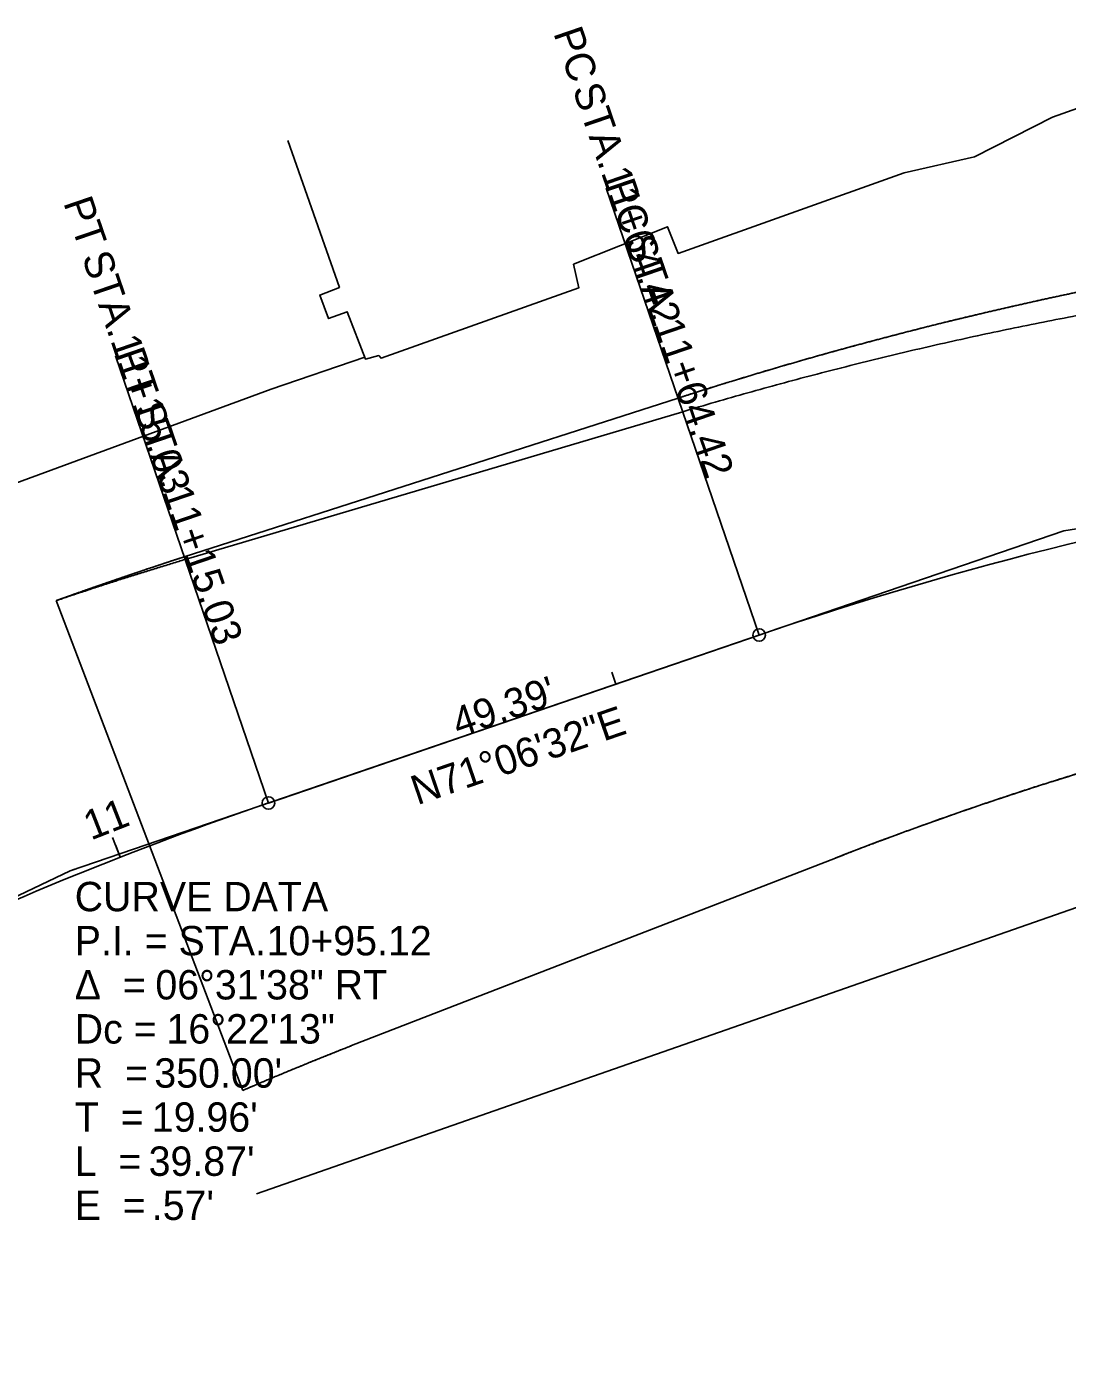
# Model space of a CAD drawing. Extents: x 219353 to 221640, y 361458 to 364236.
# Drawn here: x 220356.8 to 220456, y 362065.1 to 362191 of the extents above; entities that cross this region are included whole.
import ezdxf

# ---------------------------------------------------------------- set-up
doc = ezdxf.new("R2010")
doc.units = 0
for name, color, linetype in [('Default', 7, 'Continuous'), ('DR_P_Cells', 7, 'Continuous'), ('DR_P_GenericNode', 7, 'Continuous'), ('DR_X_Cells', 7, 'Continuous'), ('DR_X_GenericNode', 7, 'Continuous'), ('DR_X_Storm_Sewer', 7, 'Continuous'), ('DT_X_Contour_Major', 7, 'Continuous'), ('DT_X_Contour_Minor', 7, 'Continuous'), ('SC_ProfileRun1', 7, 'Continuous'), ('SC_ProfileRun2', 7, 'Continuous'), ('SC_ProfileRun3', 7, 'Continuous'), ('SC_Scratch1', 7, 'Continuous'), ('UT_X_San_Storm_Line', 7, 'Continuous'), ('UT_X_Sanitary_Cells', 7, 'Continuous'), ('UT_X_Sanitary_Line', 7, 'Continuous')]:
    doc.layers.add(name, color=color, linetype=linetype)

msp = doc.modelspace()

# ---------------------------------------------------------------- linework, layer by layer
at = {"layer": 'Default'}
for points in [[(220418.89, 362155.61), (220419.93, 362155.94), (220422, 362156.61), (220425.12, 362157.57), (220428.25, 362158.5), (220431.39, 362159.41), (220434.53, 362160.29), (220437.68, 362161.14), (220440.84, 362161.96), (220444, 362162.76), (220447.17, 362163.53), (220450.35, 362164.27), (220453.53, 362164.98), (220456.72, 362165.67), (220459.91, 362166.33), (220463.11, 362166.95), (220466.31, 362167.56), (220469.52, 362168.13), (220472.73, 362168.67), (220475.95, 362169.19), (220479.17, 362169.68), (220481.32, 362169.98), (220482.39, 362170.13)], [(220359.67, 362136.33), (220359.87, 362136.4), (220360.27, 362136.54), (220360.88, 362136.76), (220361.49, 362136.98), (220362.1, 362137.19), (220362.7, 362137.41), (220363.31, 362137.62), (220363.92, 362137.83), (220364.53, 362138.04), (220365.14, 362138.25), (220365.75, 362138.46), (220366.36, 362138.67), (220366.97, 362138.88), (220367.58, 362139.08), (220368.19, 362139.29), (220368.8, 362139.49), (220369.41, 362139.69), (220370.02, 362139.9), (220370.64, 362140.1), (220371.25, 362140.3), (220371.66, 362140.43), (220371.86, 362140.49)], [(220488.46, 362127.86), (220487.52, 362127.67), (220485.66, 362127.29), (220482.86, 362126.68), (220480.08, 362126.06), (220477.3, 362125.41), (220474.52, 362124.73), (220471.76, 362124.03), (220469, 362123.31), (220466.25, 362122.57), (220463.5, 362121.8), (220460.77, 362121.01), (220458.04, 362120.19), (220455.32, 362119.35), (220452.61, 362118.49), (220449.91, 362117.61), (220447.21, 362116.7), (220444.53, 362115.77), (220441.85, 362114.81), (220439.18, 362113.84), (220436.53, 362112.84), (220434.76, 362112.15), (220433.88, 362111.81)], [(220387.79, 362093.94), (220387.62, 362093.87), (220387.27, 362093.73), (220386.75, 362093.53), (220386.23, 362093.32), (220385.71, 362093.11), (220385.19, 362092.9), (220384.67, 362092.7), (220384.15, 362092.49), (220383.63, 362092.27), (220383.12, 362092.06), (220382.6, 362091.85), (220382.08, 362091.64), (220381.56, 362091.42), (220381.05, 362091.21), (220380.53, 362090.99), (220380.02, 362090.78), (220379.5, 362090.56), (220378.99, 362090.34), (220378.47, 362090.12), (220377.96, 362089.9), (220377.61, 362089.75), (220377.44, 362089.68)]]:
    msp.add_open_spline(points, degree=3, dxfattribs=at)
at = {"layer": 'DR_X_Cells'}
for p, q in [((220426.61, 362133.05), (220412.04, 362175.62)), ((220379.88, 362117.05), (220365.31, 362159.63))]:
    msp.add_line(p, q, dxfattribs=at)
for centre in [(220426.61, 362133.05), (220379.88, 362117.05)]:
    msp.add_circle(centre, 0.6, dxfattribs=at)
at = {"layer": 'DR_X_GenericNode'}
for p, q in [((220371.95, 362140.24), (220419.33, 362154.32)), ((220433.88, 362111.81), (220387.79, 362093.94))]:
    msp.add_line(p, q, dxfattribs=at)
for points in [[(220419.33, 362154.32), (220420.36, 362154.62), (220422.43, 362155.24), (220425.53, 362156.12), (220428.63, 362156.98), (220431.75, 362157.81), (220434.87, 362158.61), (220437.99, 362159.39), (220441.12, 362160.14), (220444.26, 362160.86), (220447.4, 362161.56), (220450.54, 362162.22), (220453.69, 362162.86), (220456.85, 362163.47), (220460.01, 362164.06), (220463.17, 362164.61), (220466.34, 362165.14), (220469.51, 362165.64), (220472.68, 362166.12), (220475.86, 362166.56), (220479.03, 362166.98), (220481.16, 362167.24), (220521.18, 362173.46)], [(220359.67, 362136.33), (220359.87, 362136.39), (220360.28, 362136.53), (220360.89, 362136.74), (220361.5, 362136.94), (220362.11, 362137.14), (220362.73, 362137.34), (220363.34, 362137.55), (220363.95, 362137.75), (220364.57, 362137.94), (220365.18, 362138.14), (220365.79, 362138.34), (220366.41, 362138.53), (220367.02, 362138.73), (220367.64, 362138.92), (220368.25, 362139.11), (220368.87, 362139.3), (220369.48, 362139.49), (220370.1, 362139.68), (220370.72, 362139.87), (220371.33, 362140.06), (220371.74, 362140.18), (220371.95, 362140.24)]]:
    msp.add_open_spline(points, degree=3, dxfattribs=at)
at = {"layer": 'DT_X_Contour_Major'}
for p, q in [((220455.61, 362142.97), (220572.38, 362161.22)), ((220361, 362110.59), (220455.61, 362142.97)), ((220379.88, 362117.05), (220426.61, 362133.05)), ((220379.88, 362117.05), (220426.61, 362133.05)), ((220238.34, 362052.3), (220361, 362110.59)), ((220361, 362110.59), (220361.44, 362110.74))]:
    msp.add_line(p, q, dxfattribs=at)
for centre, start, end in [((220539.93, 361801.9), 98.8811, 108.8911), ((220539.93, 361801.9), 98.8811, 108.8911), ((220493.2, 361785.91), 108.8911, 115.4184), ((220493.2, 361785.91), 108.8911, 115.4184)]:
    msp.add_arc(centre, 350, start, end, dxfattribs=at)
at = {"layer": 'DT_X_Contour_Minor'}
for p, q in [((220380.13, 362156.46), (220389.05, 362159.51)), ((220346.48, 362144.09), (220380.13, 362156.46)), ((220371.86, 362140.49), (220418.89, 362155.61)), ((220371.86, 362140.49), (220418.89, 362155.61)), ((220371.86, 362140.49), (220418.89, 362155.61)), ((220371.86, 362140.49), (220418.89, 362155.61)), ((220371.86, 362140.49), (220418.89, 362155.61)), ((220387.79, 362093.94), (220433.88, 362111.81)), ((220433.88, 362111.81), (220387.79, 362093.94)), ((220378.74, 362079.82), (220464.36, 362109.73))]:
    msp.add_line(p, q, dxfattribs=at)
msp.add_lwpolyline([(220381.73, 362180.14), (220386.63, 362166.16), (220384.77, 362165.43), (220385.6, 362163.18), (220387.39, 362163.83), (220389.12, 362159.33), (220390.38, 362159.67), (220390.6, 362159.41), (220409.45, 362166.12), (220408.93, 362168.36), (220417.87, 362171.93), (220418.88, 362169.4), (220440.41, 362177.07), (220447.12, 362178.59), (220454.55, 362182.38), (220459.81, 362184.23)], dxfattribs=at)
for points in [[(220418.89, 362155.61), (220419.93, 362155.94), (220422, 362156.61), (220425.12, 362157.57), (220428.25, 362158.5), (220431.39, 362159.41), (220434.53, 362160.29), (220437.68, 362161.14), (220440.84, 362161.96), (220444, 362162.76), (220447.17, 362163.53), (220450.35, 362164.27), (220453.53, 362164.98), (220456.72, 362165.67), (220459.91, 362166.33), (220463.11, 362166.95), (220466.31, 362167.56), (220469.52, 362168.13), (220472.73, 362168.67), (220475.95, 362169.19), (220479.17, 362169.68), (220481.32, 362169.98), (220482.39, 362170.13)], [(220418.89, 362155.61), (220419.93, 362155.94), (220422, 362156.61), (220425.12, 362157.57), (220428.25, 362158.5), (220431.39, 362159.41), (220434.53, 362160.29), (220437.68, 362161.14), (220440.84, 362161.96), (220444, 362162.76), (220447.17, 362163.53), (220450.35, 362164.27), (220453.53, 362164.98), (220456.72, 362165.67), (220459.91, 362166.33), (220463.11, 362166.95), (220466.31, 362167.56), (220469.52, 362168.13), (220472.73, 362168.67), (220475.95, 362169.19), (220479.17, 362169.68), (220481.32, 362169.98), (220482.39, 362170.13)], [(220418.89, 362155.61), (220419.93, 362155.94), (220422, 362156.61), (220425.12, 362157.57), (220428.25, 362158.5), (220431.39, 362159.41), (220434.53, 362160.29), (220437.68, 362161.14), (220440.84, 362161.96), (220444, 362162.76), (220447.17, 362163.53), (220450.35, 362164.27), (220453.53, 362164.98), (220456.72, 362165.67), (220459.91, 362166.33), (220463.11, 362166.95), (220466.31, 362167.56), (220469.52, 362168.13), (220472.73, 362168.67), (220475.95, 362169.19), (220479.17, 362169.68), (220481.32, 362169.98), (220482.39, 362170.13)], [(220418.89, 362155.61), (220419.93, 362155.94), (220422, 362156.61), (220425.12, 362157.57), (220428.25, 362158.5), (220431.39, 362159.41), (220434.53, 362160.29), (220437.68, 362161.14), (220440.84, 362161.96), (220444, 362162.76), (220447.17, 362163.53), (220450.35, 362164.27), (220453.53, 362164.98), (220456.72, 362165.67), (220459.91, 362166.33), (220463.11, 362166.95), (220466.31, 362167.56), (220469.52, 362168.13), (220472.73, 362168.67), (220475.95, 362169.19), (220479.17, 362169.68), (220481.32, 362169.98), (220482.39, 362170.13)], [(220359.67, 362136.33), (220359.87, 362136.4), (220360.27, 362136.54), (220360.88, 362136.76), (220361.49, 362136.98), (220362.1, 362137.19), (220362.7, 362137.41), (220363.31, 362137.62), (220363.92, 362137.83), (220364.53, 362138.04), (220365.14, 362138.25), (220365.75, 362138.46), (220366.36, 362138.67), (220366.97, 362138.88), (220367.58, 362139.08), (220368.19, 362139.29), (220368.8, 362139.49), (220369.41, 362139.69), (220370.02, 362139.9), (220370.64, 362140.1), (220371.25, 362140.3), (220371.66, 362140.43), (220371.86, 362140.49)], [(220359.67, 362136.33), (220359.87, 362136.4), (220360.27, 362136.54), (220360.88, 362136.76), (220361.49, 362136.98), (220362.1, 362137.19), (220362.7, 362137.41), (220363.31, 362137.62), (220363.92, 362137.83), (220364.53, 362138.04), (220365.14, 362138.25), (220365.75, 362138.46), (220366.36, 362138.67), (220366.97, 362138.88), (220367.58, 362139.08), (220368.19, 362139.29), (220368.8, 362139.49), (220369.41, 362139.69), (220370.02, 362139.9), (220370.64, 362140.1), (220371.25, 362140.3), (220371.66, 362140.43), (220371.86, 362140.49)], [(220359.67, 362136.33), (220359.87, 362136.4), (220360.27, 362136.54), (220360.88, 362136.76), (220361.49, 362136.98), (220362.1, 362137.19), (220362.7, 362137.41), (220363.31, 362137.62), (220363.92, 362137.83), (220364.53, 362138.04), (220365.14, 362138.25), (220365.75, 362138.46), (220366.36, 362138.67), (220366.97, 362138.88), (220367.58, 362139.08), (220368.19, 362139.29), (220368.8, 362139.49), (220369.41, 362139.69), (220370.02, 362139.9), (220370.64, 362140.1), (220371.25, 362140.3), (220371.66, 362140.43), (220371.86, 362140.49)], [(220359.67, 362136.33), (220359.87, 362136.4), (220360.27, 362136.54), (220360.88, 362136.76), (220361.49, 362136.98), (220362.1, 362137.19), (220362.7, 362137.41), (220363.31, 362137.62), (220363.92, 362137.83), (220364.53, 362138.04), (220365.14, 362138.25), (220365.75, 362138.46), (220366.36, 362138.67), (220366.97, 362138.88), (220367.58, 362139.08), (220368.19, 362139.29), (220368.8, 362139.49), (220369.41, 362139.69), (220370.02, 362139.9), (220370.64, 362140.1), (220371.25, 362140.3), (220371.66, 362140.43), (220371.86, 362140.49)], [(220433.88, 362111.81), (220434.76, 362112.15), (220436.53, 362112.84), (220439.18, 362113.84), (220441.85, 362114.81), (220444.53, 362115.77), (220447.21, 362116.7), (220449.91, 362117.61), (220452.61, 362118.49), (220455.32, 362119.35), (220458.04, 362120.19), (220460.77, 362121.01), (220463.5, 362121.8), (220466.25, 362122.57), (220469, 362123.31), (220471.76, 362124.03), (220474.52, 362124.73), (220477.3, 362125.41), (220480.08, 362126.06), (220482.86, 362126.68), (220485.66, 362127.29), (220487.52, 362127.67), (220488.46, 362127.86)], [(220488.46, 362127.86), (220487.52, 362127.67), (220485.66, 362127.29), (220482.86, 362126.68), (220480.08, 362126.06), (220477.3, 362125.41), (220474.52, 362124.73), (220471.76, 362124.03), (220469, 362123.31), (220466.25, 362122.57), (220463.5, 362121.8), (220460.77, 362121.01), (220458.04, 362120.19), (220455.32, 362119.35), (220452.61, 362118.49), (220449.91, 362117.61), (220447.21, 362116.7), (220444.53, 362115.77), (220441.85, 362114.81), (220439.18, 362113.84), (220436.53, 362112.84), (220434.76, 362112.15), (220433.88, 362111.81)], [(220377.44, 362089.68), (220377.61, 362089.75), (220377.96, 362089.9), (220378.47, 362090.12), (220378.99, 362090.34), (220379.5, 362090.56), (220380.02, 362090.78), (220380.53, 362090.99), (220381.05, 362091.21), (220381.56, 362091.42), (220382.08, 362091.64), (220382.6, 362091.85), (220383.12, 362092.06), (220383.63, 362092.27), (220384.15, 362092.49), (220384.67, 362092.7), (220385.19, 362092.9), (220385.71, 362093.11), (220386.23, 362093.32), (220386.75, 362093.53), (220387.27, 362093.73), (220387.62, 362093.87), (220387.79, 362093.94)], [(220387.79, 362093.94), (220387.62, 362093.87), (220387.27, 362093.73), (220386.75, 362093.53), (220386.23, 362093.32), (220385.71, 362093.11), (220385.19, 362092.9), (220384.67, 362092.7), (220384.15, 362092.49), (220383.63, 362092.27), (220383.12, 362092.06), (220382.6, 362091.85), (220382.08, 362091.64), (220381.56, 362091.42), (220381.05, 362091.21), (220380.53, 362090.99), (220380.02, 362090.78), (220379.5, 362090.56), (220378.99, 362090.34), (220378.47, 362090.12), (220377.96, 362089.9), (220377.61, 362089.75), (220377.44, 362089.68)]]:
    msp.add_open_spline(points, degree=3, dxfattribs=at)
at = {"layer": 'SC_ProfileRun2'}
for p, q in [((220426.61, 362133.05), (220412.04, 362175.62)), ((220379.88, 362117.05), (220365.31, 362159.63))]:
    msp.add_line(p, q, dxfattribs=at)
for centre in [(220426.61, 362133.05), (220379.88, 362117.05)]:
    msp.add_circle(centre, 0.6, dxfattribs=at)
at = {"layer": 'SC_ProfileRun3'}
msp.add_line((220365.77, 362111.88), (220365.33, 362113), dxfattribs=at)
at = {"layer": 'UT_X_San_Storm_Line'}
for p, q in [((220371.86, 362140.49), (220418.89, 362155.61)), ((220433.88, 362111.81), (220387.79, 362093.94))]:
    msp.add_line(p, q, dxfattribs=at)
for points in [[(220418.89, 362155.61), (220419.48, 362155.8), (220421.52, 362156.46), (220425.24, 362157.6), (220428.2, 362158.49), (220431.38, 362159.41), (220434.51, 362160.28), (220437.66, 362161.13), (220440.82, 362161.96), (220443.98, 362162.76), (220447.15, 362163.52), (220450.32, 362164.26), (220453.51, 362164.98), (220456.69, 362165.66), (220459.89, 362166.32), (220463.09, 362166.95), (220466.3, 362167.55), (220469.49, 362168.12), (220472.76, 362168.68), (220475.81, 362169.17), (220479.66, 362169.75), (220481.78, 362170.05), (220482.39, 362170.13)], [(220359.67, 362136.33), (220359.78, 362136.37), (220360.18, 362136.51), (220360.91, 362136.77), (220361.48, 362136.98), (220362.1, 362137.19), (220362.7, 362137.41), (220363.31, 362137.62), (220363.92, 362137.83), (220364.53, 362138.04), (220365.14, 362138.25), (220365.75, 362138.46), (220366.36, 362138.67), (220366.97, 362138.88), (220367.58, 362139.08), (220368.19, 362139.29), (220368.8, 362139.49), (220369.41, 362139.69), (220370.03, 362139.9), (220370.61, 362140.09), (220371.34, 362140.33), (220371.75, 362140.46), (220371.86, 362140.49)], [(220488.46, 362127.86), (220487.93, 362127.75), (220486.1, 362127.38), (220482.77, 362126.66), (220480.13, 362126.07), (220477.32, 362125.41), (220474.57, 362124.74), (220471.8, 362124.05), (220469.05, 362123.33), (220466.3, 362122.58), (220463.55, 362121.81), (220460.82, 362121.02), (220458.09, 362120.21), (220455.37, 362119.37), (220452.65, 362118.51), (220449.95, 362117.62), (220447.25, 362116.71), (220444.57, 362115.78), (220441.84, 362114.81), (220439.31, 362113.88), (220436.12, 362112.69), (220434.38, 362112.01), (220433.88, 362111.81)], [(220387.79, 362093.94), (220387.7, 362093.9), (220387.35, 362093.76), (220386.73, 362093.52), (220386.24, 362093.32), (220385.71, 362093.11), (220385.19, 362092.91), (220384.67, 362092.7), (220384.15, 362092.49), (220383.64, 362092.28), (220383.12, 362092.06), (220382.6, 362091.85), (220382.08, 362091.64), (220381.57, 362091.42), (220381.05, 362091.21), (220380.53, 362090.99), (220380.02, 362090.78), (220379.5, 362090.56), (220378.98, 362090.34), (220378.49, 362090.13), (220377.88, 362089.87), (220377.54, 362089.72), (220377.44, 362089.68)]]:
    msp.add_open_spline(points, degree=2, dxfattribs=at)
at = {"layer": 'UT_X_Sanitary_Cells'}
for p, q in [((220412.97, 362128.38), (220412.58, 362129.51)), ((220365.77, 362111.88), (220365.04, 362113.75))]:
    msp.add_line(p, q, dxfattribs=at)
at = {"layer": 'UT_X_Sanitary_Line'}
msp.add_line((220359.67, 362136.33), (220377.44, 362089.68), dxfattribs=at)

# ---------------------------------------------------------------- texts
at = {"layer": 'DR_P_Cells'}
msp.add_text("49.39'", height=2.8, rotation=18.8911, dxfattribs=at).set_placement((220397.97, 362123.29))
at = {"layer": 'DR_P_GenericNode'}
msp.add_text("49.39'", height=2.8, rotation=18.8911, dxfattribs=at).set_placement((220397.97, 362123.29))
at = {"layer": 'DR_X_Cells'}
for s, p in [('PC', (220411.98, 362175.93)), (' STA. ', (220413.47, 362171.59)), ('11+64.42', (220416.53, 362162.64)), ('PT', (220365.28, 362159.85)), (' STA. ', (220366.71, 362155.67)), ('11+15.03', (220369.77, 362146.73))]:
    msp.add_text(s, height=2.8, rotation=288.8911, dxfattribs=at).set_placement(p)
at = {"layer": 'DR_X_Storm_Sewer'}
for s, p in [('CURVE DATA', (220361.43, 362106.74)), ('P.I. = STA. ', (220361.43, 362102.54)), ('10+95.12', (220379.7, 362102.54)), ('Δ  = ', (220361.43, 362098.34)), ('06°31\'38" RT', (220369.11, 362098.34)), ('Dc = ', (220361.43, 362094.14)), ('16°22\'13"', (220370.17, 362094.14)), ('R  = ', (220361.43, 362089.94)), ("350.00'", (220369.01, 362089.94)), ('T  = ', (220361.43, 362085.74)), ("19.96'", (220368.77, 362085.74)), ('L  = ', (220361.43, 362081.54)), ("39.87'", (220368.47, 362081.54)), ('E  = ', (220361.43, 362077.34)), (".57'", (220368.77, 362077.34))]:
    msp.add_text(s, height=2.8, dxfattribs=at).set_placement(p)
at = {"layer": 'SC_ProfileRun1'}
msp.add_text('N71°06\'32"E', height=2.8, rotation=18.8911, dxfattribs=at).set_placement((220394.05, 362116.83))
at = {"layer": 'SC_ProfileRun2'}
for s, p in [('PC', (220406.99, 362190.39)), (' STA. ', (220408.47, 362186.06)), ('11+64.42', (220411.53, 362177.11)), ('PT', (220360.32, 362174.23)), (' STA. ', (220361.75, 362170.05)), ('11+15.03', (220364.81, 362161.11))]:
    msp.add_text(s, height=2.8, rotation=288.8911, dxfattribs=at).set_placement(p)
at = {"layer": 'SC_Scratch1'}
msp.add_text('N71°06\'32"E', height=2.8, rotation=18.8911, dxfattribs=at).set_placement((220394.05, 362116.83))
at = {"layer": 'UT_X_Sanitary_Cells'}
msp.add_text('11', height=2.8, rotation=21.3517, dxfattribs=at).set_placement((220362.97, 362113.47))

doc.saveas('drawing.dxf')
